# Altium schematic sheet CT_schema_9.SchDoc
size 405 x 220 mm
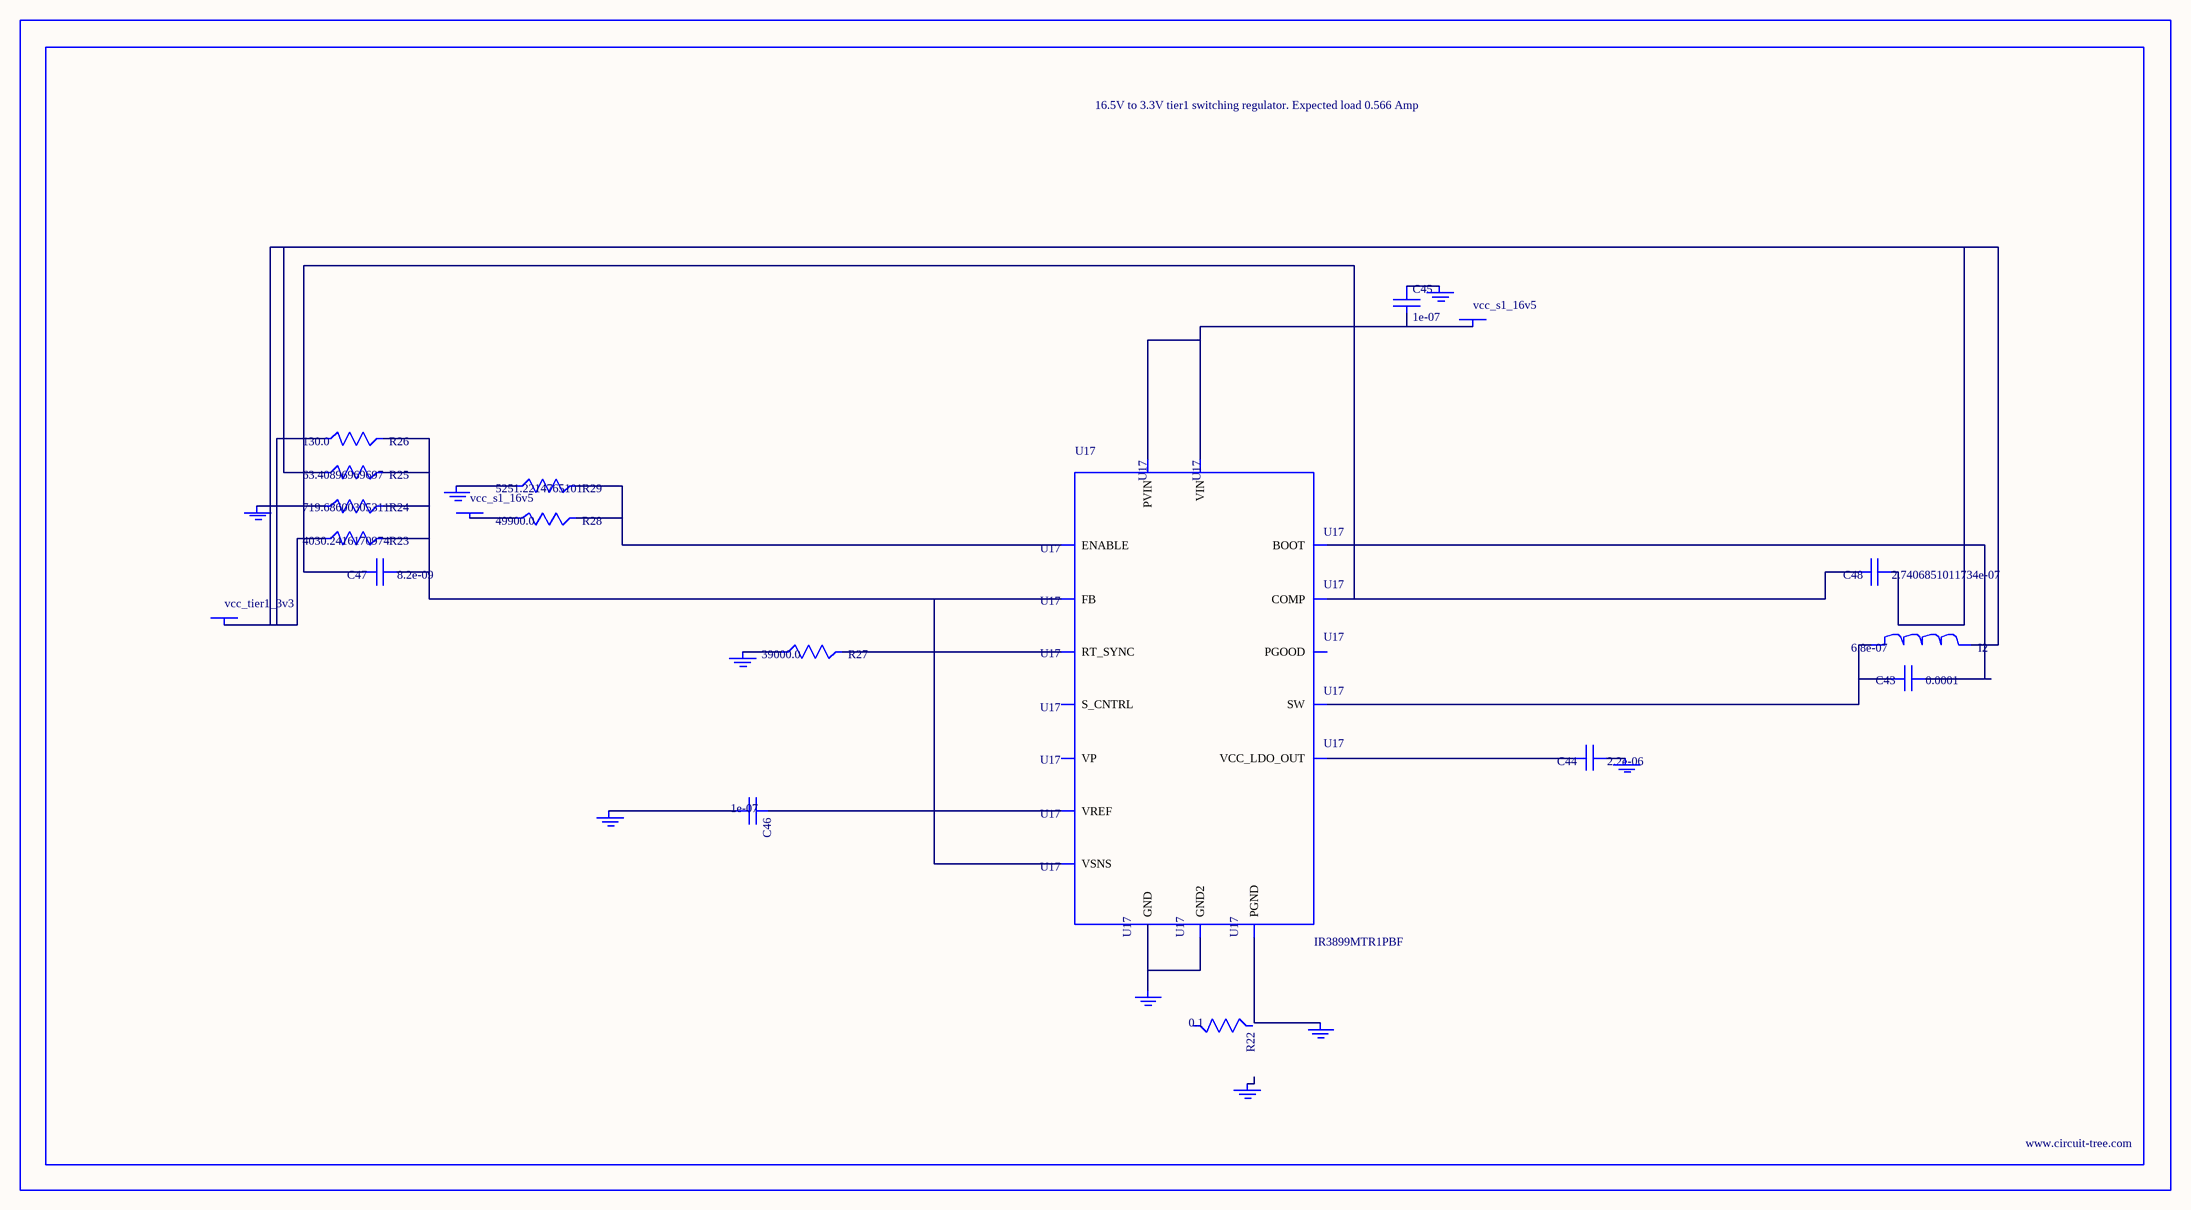
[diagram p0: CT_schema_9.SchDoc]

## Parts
BORDER8  (no value)
C43  0.0001  [C1210]
C44  2.2e-06  [C0603]
C45  1e-07  [C0402]
C46  1e-07  [C0402]
C47  8.2e-09  [C0402]
C48  2.7406851011734e-07  [R0603]
GND_INSTANCE_8_0  (no value)
GND_INSTANCE_8_1  (no value)
GND_INSTANCE_8_2  (no value)
GND_INSTANCE_8_3  (no value)
GND_INSTANCE_8_4  (no value)
GND_INSTANCE_8_5  (no value)
GND_INSTANCE_8_6  (no value)
GND_INSTANCE_8_7  (no value)
GND_INSTANCE_8_8  (no value)
I2  6.8e-07  [IND25X25CZ]
POWER_INSTANCE_8_0  vcc_s1_16v5
POWER_INSTANCE_8_1  vcc_s1_16v5
POWER_INSTANCE_8_2  vcc_tier1_3v3
R22  0.1  [R0603]
R23  4030.2416170974  [R0603]
R24  719.68600305311  [R0603]
R25  63.40896969697  [R0603]
R26  130.0  [R0603]
R27  39000.0  [R0603]
R28  49900.0  [R0603]
R29  5251.2214765101  [R0603]
U17  IR3899MTR1PBF  [IR3899MTR1PBF]

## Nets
NetC43_1: C43.1 U17.14(BOOT)
NetC43_2: C43.2 I2.1 U17.12(SW)
NetC44_1: C44.1 GND_INSTANCE_8_4.0(GND)
NetC44_2: C44.2 U17.10(VCC_LDO_OUT)
NetC45_1: C45.1 GND_INSTANCE_8_3.0(GND)
NetC45_2: C45.2 POWER_INSTANCE_8_0.0(PWR) U17.9(VIN) U17.13(PVIN)
NetC46_1: C46.1 U17.2(VREF)
NetC46_2: C46.2 GND_INSTANCE_8_1.0(GND)
NetC47_1: C47.1 R23.2 R24.2 R25.2 R26.2 U17.1(FB) U17.8(VSNS)
NetC47_2: C47.2 C48.2 U17.3(COMP)
NetC48_1: C48.1 I2.2 POWER_INSTANCE_8_2.0(PWR) R23.1 R25.1 R26.1
NetGND_INSTANCE_8_0_0: GND_INSTANCE_8_0.0(GND) R24.1
NetGND_INSTANCE_8_2_0: GND_INSTANCE_8_2.0(GND) R27.1
NetGND_INSTANCE_8_6_0: GND_INSTANCE_8_6.0(GND) U17.11(PGND)
NetGND_INSTANCE_8_7_0: GND_INSTANCE_8_7.0(GND) R29.1
NetGND_INSTANCE_8_8_0: GND_INSTANCE_8_8.0(GND) U17.4(GND) U17.17(GND2)
NetPOWER_INSTANCE_8_1_0: POWER_INSTANCE_8_1.0(PWR) R28.1
NetR27_2: R27.2 U17.5(RT_SYNC)
NetR28_2: R28.2 R29.2 U17.15(ENABLE)

Not connected (* = marked no-connect by the designer): GND_INSTANCE_8_5 0(GND); R22 1 2; U17 6(S_CNTRL) 7(PGOOD) 16(VP)

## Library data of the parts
BORDER8 = BORDER_PAGE8
C43 = GRM32ER61A107ME20L
C44 = C0603C225K8RACTU
C45 C46 = C0402C104K3RACTU
C47 = C0402C822K3RAC
C48 = C48
GND_INSTANCE_8_0-GND_INSTANCE_8_8 = GND
I2 = IHLP2525CZERR68M01
POWER_INSTANCE_8_0-POWER_INSTANCE_8_2 = PWR
R22 = ERJ-3RSFR10V
R23 = R23
R24 = R24
R25 = R25
R26 = RC0603JR-07130RL
R27 = RC0603JR-0739KL
R28 = RC0603FR-0749K9
R29 = R29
